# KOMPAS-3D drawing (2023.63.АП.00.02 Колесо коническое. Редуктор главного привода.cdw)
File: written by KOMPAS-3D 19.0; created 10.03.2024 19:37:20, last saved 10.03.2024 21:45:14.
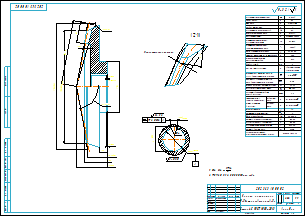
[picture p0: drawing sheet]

Sheet 1: A2, landscape

Document properties: Автор: mail.maksim@mail.ru; Знак неуказанной шероховатости: 4; Параметр неуказанной шероховатости: Rz3,2; Наименование: Колесо коническое. Редуктор главного привода; Масса: 2.558

Title block, sheet 1: Наименование: Колесо коническое. / Редуктор главного привода.; designation: 2023.63.АП.00.02; Материал: Сталь 45 ГОСТ 1050-2013; Масса: 2,56; Количество листов документа: 1; organisation: АгроПак; Форматы листов документа: A2; stored path: O:\Самозанятый. Полынский М.И\Агропак\03 Проекты 2023 года\2023.63.АП.00.00 Ремкомплект редуктора. Шестерня и вал-шестерня\2023.63.АП Чертежи\2023.63.АП.00.02 Колесо коническое. Редуктор главного привода.cdw; Разработал: Полынский; Утвердил: Гордиенко
Table, sheet 1:
  1355013179 / 778582241

Views: Вид и метод обработки, Выносной элемент
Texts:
  Ячейка таблицы
  Обозначение чертежа
  сопряженного зубчатого колеса
  Внешняя высота зуба
  Средний делительный диаметр
  Среднее конусное расстояние
  Внешнее конусное расстояние
  Угол конуса впадин
  Внешний окружной модуль
  Межосевой угол
  Относительные
  размеры суммарного
  пятна контакта
  в передаче
  Гарантированный боковой
  зазор в передаче
  Предельное отклонение шага
  Допуск на биение зубчатого венца
  Высота до делительной хорды
  зуба в измерительном сечении
  Делительная толщина зуба по
  хорде в измерительном сечении
  Развод резцов
  Номинальный диаметр
  зуборезной головки
  Степень точности по ГОСТ 1758-81
  Угол делительного конуса
  Коэффициент изменения
  расчетной толщины зуба
  Коэффициент смещения
  средний нормальный
  Исходный контур
  Направление линии зуба
  Средний угол наклона зубьев
  Осевая форма зуба
  Тип зуба
  Число зубьев
  Средний нормальный модуль
  по длине
  зуба
  по высоте
  Symbol
  m te
  f Pt
  не менее 55%
  не менее 50%
  двухсторонний
  однономерный
  ГОСТ 16202-81
  правое
  Круговой
  Таблица параметров
  Измерительное сечение
  Ra 3,2
  Rz3,2
  Rz3,2 ( )
  gliv
Dimensions and other numbers on the sheet: 15; 1,6; 2 фаски; 100; 246,736; 220; 125,32; 40; 12,1; 38,129; 45; 60,244; 80 06'51"; 11 02'27"; 2023.63.АП.00.01; 11,212; 206,74; 105,32; 74 53'45"; 6; 0,1; 0,071; 3,711; 8,581 -0,126 -0,256; 1; 200; 8-B; 78 57'33"; 0,4319; -0,5518; 41; 4,3669; 20; 14; 48,8; 1:1; 2023.63.АП.00.02; 2,56

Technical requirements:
  ТВЧ h 0,8...1,2; 50...55 HRC Э  по зубу.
